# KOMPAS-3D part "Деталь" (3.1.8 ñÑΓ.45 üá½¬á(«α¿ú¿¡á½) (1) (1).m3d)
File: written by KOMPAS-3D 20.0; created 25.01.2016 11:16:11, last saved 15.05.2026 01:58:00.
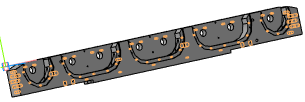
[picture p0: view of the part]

Document properties: Полное имя файла: E:\test_kompas\all_v18\3.1.8 дет.45 Балка(оригинал) (1) (1).m3d

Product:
- Part/product: Деталь
    Масса: 261.985
  - Body: Тело 1

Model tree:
1. Эскиз:1
2. Операция выдавливания:1
     Расстояние 1 = 115
3. Эскиз:9  (with: Операция выдавливания:1)
4. Вырезать элемент выдавливания:13
     Расстояние 1 = 115
5. Эскиз:19  (with: Операция выдавливания:1)
6. Вырезать элемент выдавливания:14
     Расстояние 1 = 231
7. Эскиз:20  (with: Операция выдавливания:1)
8. Эскиз:21  (with: Операция выдавливания:1)
9. Вырезать элемент выдавливания:15
     Расстояние 1 = 75
10. Вырезать элемент выдавливания:16
     Расстояние 1 = 10
11. Эскиз:22  (with: Операция выдавливания:1, Вырезать элемент выдавливания:14)
12. Вырезать элемент выдавливания:17
     Расстояние 1 = 30
13. Эскиз:23  (with: Операция выдавливания:1)
14. Вырезать элемент выдавливания:18
     Расстояние 1 = 30
15. Условное изображение резьбы:1  (with: Вырезать элемент выдавливания:17)
     Длина резьбы = 30; Шаг резьбы = 2; Номинальный диаметр резьбы = 20.0651
16. Условное изображение резьбы:2  (with: Вырезать элемент выдавливания:17)
     Длина резьбы = 30; Шаг резьбы = 2; Номинальный диаметр резьбы = 20.0651
17. Условное изображение резьбы:3  (with: Вырезать элемент выдавливания:18)
     Длина резьбы = 30; Шаг резьбы = 2; Номинальный диаметр резьбы = 20.0651
18. Условное изображение резьбы:4  (with: Вырезать элемент выдавливания:18)
     Длина резьбы = 30; Шаг резьбы = 2; Номинальный диаметр резьбы = 20.0651
19. Эскиз:24  (with: Операция выдавливания:1)
20. Вырезать элемент выдавливания:19
     Расстояние 1 = 75
21. Эскиз:25  (with: Операция выдавливания:1)
22. Вырезать элемент выдавливания:20
     Расстояние 1 = 35
23. Условное изображение резьбы:5  (with: Вырезать элемент выдавливания:20)
     Длина резьбы = 35; Шаг резьбы = 1.5; Номинальный диаметр резьбы = 20.0538
24. Условное изображение резьбы:6  (with: Вырезать элемент выдавливания:20)
     Длина резьбы = 35; Шаг резьбы = 1.5; Номинальный диаметр резьбы = 20.0538
25. Условное изображение резьбы:7  (with: Вырезать элемент выдавливания:20)
     Длина резьбы = 35; Шаг резьбы = 1.5; Номинальный диаметр резьбы = 20.0538
26. Условное изображение резьбы:8  (with: Вырезать элемент выдавливания:20)
     Длина резьбы = 35; Шаг резьбы = 1.5; Номинальный диаметр резьбы = 20.0538
27. Условное изображение резьбы:9  (with: Вырезать элемент выдавливания:20)
     Длина резьбы = 35; Шаг резьбы = 1; Номинальный диаметр резьбы = 19.5125
28. Условное изображение резьбы:10  (with: Вырезать элемент выдавливания:20)
     Длина резьбы = 35; Шаг резьбы = 1; Номинальный диаметр резьбы = 19.5125
29. Эскиз:26  (with: Операция выдавливания:1, Вырезать элемент выдавливания:13)
30. Вырезать элемент выдавливания:21
     Расстояние 1 = 35
31. Условное изображение резьбы:11  (with: Вырезать элемент выдавливания:21)
     Длина резьбы = 35; Шаг резьбы = 1.5; Номинальный диаметр резьбы = 20.0538
32. Условное изображение резьбы:12  (with: Вырезать элемент выдавливания:21)
     Длина резьбы = 35; Шаг резьбы = 1.5; Номинальный диаметр резьбы = 20.0538
33. Условное изображение резьбы:13  (with: Вырезать элемент выдавливания:21)
     Длина резьбы = 35; Шаг резьбы = 1.5; Номинальный диаметр резьбы = 20.0538
34. Условное изображение резьбы:14  (with: Вырезать элемент выдавливания:21)
     Длина резьбы = 35; Шаг резьбы = 1.5; Номинальный диаметр резьбы = 20.0538
35. Условное изображение резьбы:15  (with: Вырезать элемент выдавливания:21)
     Длина резьбы = 35; Шаг резьбы = 1.5; Номинальный диаметр резьбы = 20.0538
36. Условное изображение резьбы:16  (with: Вырезать элемент выдавливания:21)
     Длина резьбы = 35; Шаг резьбы = 1.5; Номинальный диаметр резьбы = 20.0538
37. Эскиз:27  (with: Операция выдавливания:1, Вырезать элемент выдавливания:15)
38. Эскиз:28  (with: Операция выдавливания:1)
39. Вырезать элемент выдавливания:22
     Расстояние 1 = 115
40. Эскиз:29  (with: Вырезать элемент выдавливания:16)
41. Вырезать элемент выдавливания:23
     Расстояние 1 = 13
42. Эскиз:30  (with: Вырезать элемент выдавливания:16)
43. Вырезать элемент выдавливания:24
     Расстояние 1 = 13
44. Условное изображение резьбы:17  (with: Вырезать элемент выдавливания:23)
     Длина резьбы = 13; Шаг резьбы = 1; Номинальный диаметр резьбы = 9.51253
45. Условное изображение резьбы:18  (with: Вырезать элемент выдавливания:23)
     Длина резьбы = 13; Шаг резьбы = 1; Номинальный диаметр резьбы = 9.51253
46. Условное изображение резьбы:19  (with: Вырезать элемент выдавливания:23)
     Длина резьбы = 13; Шаг резьбы = 1; Номинальный диаметр резьбы = 9.51253
47. Условное изображение резьбы:20  (with: Вырезать элемент выдавливания:23)
     Длина резьбы = 13; Шаг резьбы = 1; Номинальный диаметр резьбы = 9.51253
48. Условное изображение резьбы:21  (with: Вырезать элемент выдавливания:23)
     Длина резьбы = 13; Шаг резьбы = 1; Номинальный диаметр резьбы = 9.51253
49. Условное изображение резьбы:22  (with: Вырезать элемент выдавливания:24)
     Длина резьбы = 13; Шаг резьбы = 1; Номинальный диаметр резьбы = 9.51253
50. Условное изображение резьбы:23  (with: Вырезать элемент выдавливания:24)
     Длина резьбы = 13; Шаг резьбы = 1; Номинальный диаметр резьбы = 9.51253
51. Условное изображение резьбы:24  (with: Вырезать элемент выдавливания:24)
     Длина резьбы = 13; Шаг резьбы = 1; Номинальный диаметр резьбы = 9.51253
52. Условное изображение резьбы:25  (with: Вырезать элемент выдавливания:24)
     Длина резьбы = 13; Шаг резьбы = 1; Номинальный диаметр резьбы = 9.51253
53. Условное изображение резьбы:26  (with: Вырезать элемент выдавливания:24)
     Длина резьбы = 13; Шаг резьбы = 1; Номинальный диаметр резьбы = 9.51253
54. Эскиз:31  (with: Вырезать элемент выдавливания:16, Вырезать элемент выдавливания:19)
55. Вырезать элемент выдавливания:25
     Расстояние 1 = 13
56. Условное изображение резьбы:27  (with: Вырезать элемент выдавливания:25)
     Длина резьбы = 13; Шаг резьбы = 1; Номинальный диаметр резьбы = 9.51253
57. Условное изображение резьбы:28  (with: Вырезать элемент выдавливания:25)
     Длина резьбы = 13; Шаг резьбы = 1; Номинальный диаметр резьбы = 9.51253
58. Условное изображение резьбы:29  (with: Вырезать элемент выдавливания:25)
     Длина резьбы = 13; Шаг резьбы = 1; Номинальный диаметр резьбы = 9.51253
59. Условное изображение резьбы:30  (with: Вырезать элемент выдавливания:25)
     Длина резьбы = 13; Шаг резьбы = 1; Номинальный диаметр резьбы = 9.51253
60. Условное изображение резьбы:31  (with: Вырезать элемент выдавливания:25)
     Длина резьбы = 13; Шаг резьбы = 1; Номинальный диаметр резьбы = 9.51253
61. Условное изображение резьбы:32  (with: Вырезать элемент выдавливания:25)
     Длина резьбы = 13; Шаг резьбы = 1; Номинальный диаметр резьбы = 9.51253
62. Условное изображение резьбы:33  (with: Вырезать элемент выдавливания:25)
     Длина резьбы = 13; Шаг резьбы = 1; Номинальный диаметр резьбы = 9.51253
63. Эскиз:32  (with: Вырезать элемент выдавливания:16)
64. Вырезать элемент выдавливания:26
     Расстояние 1 = 13
65. Условное изображение резьбы:34  (with: Вырезать элемент выдавливания:26)
     Длина резьбы = 13; Шаг резьбы = 1; Номинальный диаметр резьбы = 9.51253
66. Условное изображение резьбы:35  (with: Вырезать элемент выдавливания:26)
     Длина резьбы = 13; Шаг резьбы = 1; Номинальный диаметр резьбы = 9.51253
67. Условное изображение резьбы:36  (with: Вырезать элемент выдавливания:26)
     Длина резьбы = 13; Шаг резьбы = 1; Номинальный диаметр резьбы = 9.51253
68. Условное изображение резьбы:37  (with: Вырезать элемент выдавливания:26)
     Длина резьбы = 13; Шаг резьбы = 1; Номинальный диаметр резьбы = 9.51253
69. Условное изображение резьбы:38  (with: Вырезать элемент выдавливания:26)
     Длина резьбы = 13; Шаг резьбы = 1; Номинальный диаметр резьбы = 9.51253
70. Условное изображение резьбы:39  (with: Вырезать элемент выдавливания:26)
     Длина резьбы = 13; Шаг резьбы = 1; Номинальный диаметр резьбы = 9.51253
71. Условное изображение резьбы:40  (with: Вырезать элемент выдавливания:26)
     Длина резьбы = 13; Шаг резьбы = 1; Номинальный диаметр резьбы = 9.51253
72. Эскиз:33  (with: Вырезать элемент выдавливания:16)
73. Вырезать элемент выдавливания:27
     Расстояние 1 = 13
74. Условное изображение резьбы:41  (with: Вырезать элемент выдавливания:27)
     Длина резьбы = 13; Шаг резьбы = 1; Номинальный диаметр резьбы = 9.51253
75. Условное изображение резьбы:42  (with: Вырезать элемент выдавливания:27)
     Длина резьбы = 13; Шаг резьбы = 1; Номинальный диаметр резьбы = 9.51253
76. Условное изображение резьбы:43  (with: Вырезать элемент выдавливания:27)
     Длина резьбы = 13; Шаг резьбы = 1; Номинальный диаметр резьбы = 9.51253
77. Условное изображение резьбы:44  (with: Вырезать элемент выдавливания:27)
     Длина резьбы = 13; Шаг резьбы = 1; Номинальный диаметр резьбы = 9.51253
78. Условное изображение резьбы:45  (with: Вырезать элемент выдавливания:27)
     Длина резьбы = 13; Шаг резьбы = 1; Номинальный диаметр резьбы = 9.51253
79. Условное изображение резьбы:46  (with: Вырезать элемент выдавливания:27)
     Длина резьбы = 13; Шаг резьбы = 1; Номинальный диаметр резьбы = 9.51253
80. Условное изображение резьбы:47  (with: Вырезать элемент выдавливания:27)
     Длина резьбы = 13; Шаг резьбы = 1; Номинальный диаметр резьбы = 9.51253
81. Эскиз:34  (with: Операция выдавливания:1)
82. Эскиз:35  (with: Операция выдавливания:1, Вырезать элемент выдавливания:17)
83. Вырезать элемент выдавливания:28
     Расстояние 1 = 94
84. Эскиз:36  (with: Операция выдавливания:1)
85. Вырезать элемент выдавливания:29
     Расстояние 1 = 21
86. Эскиз:37  (with: Вырезать элемент выдавливания:15)
87. Вырезать элемент выдавливания:30
     Расстояние 1 = 40
88. Эскиз:38  (with: Операция выдавливания:1)
89. Вырезать элемент выдавливания:31
     Расстояние 1 = 10
90. Эскиз:39  (with: Операция выдавливания:1)
91. Вырезать элемент выдавливания:32
     Расстояние 1 = 50
92. Условное изображение резьбы:48  (with: Вырезать элемент выдавливания:32)
     Длина резьбы = 50; Шаг резьбы = 1; Номинальный диаметр резьбы = 18.0325
93. Условное изображение резьбы:49  (with: Вырезать элемент выдавливания:32)
     Длина резьбы = 50; Шаг резьбы = 1; Номинальный диаметр резьбы = 18.0325
94. Условное изображение резьбы:50  (with: Вырезать элемент выдавливания:32)
     Длина резьбы = 50; Шаг резьбы = 1; Номинальный диаметр резьбы = 18.0325
95. Условное изображение резьбы:51  (with: Вырезать элемент выдавливания:32)
     Длина резьбы = 50; Шаг резьбы = 1; Номинальный диаметр резьбы = 18.0325
96. Эскиз:40  (with: Операция выдавливания:1, Вырезать элемент выдавливания:13, Вырезать элемент выдавливания:22, Вырезать элемент выдавливания:29)
97. Вырезать элемент выдавливания:33
     Расстояние 1 = 70
98. Условное изображение резьбы:52  (with: Вырезать элемент выдавливания:33)
     Длина резьбы = 70; Шаг резьбы = 1; Номинальный диаметр резьбы = 28.0325
99. Условное изображение резьбы:53  (with: Вырезать элемент выдавливания:33)
     Длина резьбы = 70; Шаг резьбы = 1; Номинальный диаметр резьбы = 28.0325
100. Эскиз:41  (with: Операция выдавливания:1)
101. Вырезать элемент выдавливания:34
     Расстояние 1 = 30
102. Условное изображение резьбы:54  (with: Вырезать элемент выдавливания:34)
     Длина резьбы = 30; Шаг резьбы = 1; Номинальный диаметр резьбы = 8.03253
103. Условное изображение резьбы:55  (with: Вырезать элемент выдавливания:34)
     Длина резьбы = 30; Шаг резьбы = 1; Номинальный диаметр резьбы = 8.03253
104. Условное изображение резьбы:56  (with: Вырезать элемент выдавливания:34)
     Длина резьбы = 30; Шаг резьбы = 1; Номинальный диаметр резьбы = 8.03253
105. Условное изображение резьбы:57  (with: Вырезать элемент выдавливания:34)
     Длина резьбы = 30; Шаг резьбы = 1; Номинальный диаметр резьбы = 8.03253
106. Условное изображение резьбы:58  (with: Вырезать элемент выдавливания:34)
     Длина резьбы = 30; Шаг резьбы = 1; Номинальный диаметр резьбы = 8.03253
107. Вырезать элемент выдавливания:35
     Расстояние 1 = 10
108. Эскиз:42  (with: Операция выдавливания:1, Вырезать элемент выдавливания:33)
109. Вырезать элемент выдавливания:36
     Расстояние 1 = 55
110. Условное изображение резьбы:59  (with: Вырезать элемент выдавливания:36)
     Длина резьбы = 55; Шаг резьбы = 1; Номинальный диаметр резьбы = 16.0325
111. Эскиз:43  (with: Операция выдавливания:1, Вырезать элемент выдавливания:22)
112. Вырезать элемент выдавливания:37
     Расстояние 1 = 30
113. Условное изображение резьбы:60  (with: Вырезать элемент выдавливания:37)
     Длина резьбы = 30; Шаг резьбы = 1; Номинальный диаметр резьбы = 11.0325
114. Условное изображение резьбы:61  (with: Вырезать элемент выдавливания:37)
     Длина резьбы = 30; Шаг резьбы = 1; Номинальный диаметр резьбы = 11.0325
115. Условное изображение резьбы:62  (with: Вырезать элемент выдавливания:37)
     Длина резьбы = 30; Шаг резьбы = 1; Номинальный диаметр резьбы = 11.0325
116. Условное изображение резьбы:63  (with: Вырезать элемент выдавливания:37)
     Длина резьбы = 30; Шаг резьбы = 1; Номинальный диаметр резьбы = 11.0325
117. Условное изображение резьбы:64  (with: Вырезать элемент выдавливания:37)
     Длина резьбы = 30; Шаг резьбы = 1; Номинальный диаметр резьбы = 11.0325
118. Условное изображение резьбы:65  (with: Вырезать элемент выдавливания:37)
     Длина резьбы = 30; Шаг резьбы = 1; Номинальный диаметр резьбы = 11.0325
119. Условное изображение резьбы:66  (with: Вырезать элемент выдавливания:37)
     Длина резьбы = 30; Шаг резьбы = 1; Номинальный диаметр резьбы = 11.0325
120. Условное изображение резьбы:67  (with: Вырезать элемент выдавливания:37)
     Длина резьбы = 30; Шаг резьбы = 1; Номинальный диаметр резьбы = 11.0325
121. Условное изображение резьбы:68  (with: Вырезать элемент выдавливания:37)
     Длина резьбы = 30; Шаг резьбы = 1; Номинальный диаметр резьбы = 11.0325
122. Условное изображение резьбы:69  (with: Вырезать элемент выдавливания:37)
     Длина резьбы = 30; Шаг резьбы = 1; Номинальный диаметр резьбы = 11.0325
123. Условное изображение резьбы:70  (with: Вырезать элемент выдавливания:37)
     Длина резьбы = 30; Шаг резьбы = 1; Номинальный диаметр резьбы = 11.0325
124. Условное изображение резьбы:71  (with: Вырезать элемент выдавливания:37)
     Длина резьбы = 30; Шаг резьбы = 1; Номинальный диаметр резьбы = 11.0325
125. Условное изображение резьбы:72  (with: Вырезать элемент выдавливания:37)
     Длина резьбы = 30; Шаг резьбы = 1; Номинальный диаметр резьбы = 11.0325
126. Условное изображение резьбы:73  (with: Вырезать элемент выдавливания:37)
     Длина резьбы = 30; Шаг резьбы = 1; Номинальный диаметр резьбы = 11.0325
127. Условное изображение резьбы:74  (with: Вырезать элемент выдавливания:37)
     Длина резьбы = 30; Шаг резьбы = 1; Номинальный диаметр резьбы = 11.0325
128. Условное изображение резьбы:75  (with: Вырезать элемент выдавливания:37)  (labels: 4061045924-6285-0-0|0)
     Длина резьбы = 30; Шаг резьбы = 1; Номинальный диаметр резьбы = 11.0325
